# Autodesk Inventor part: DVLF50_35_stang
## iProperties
Created: 2010-03
Part Number: DVLF50_35_stang
Document SubType Name: Modeling
Designer: TB
Mass: 264.807 g
Surface Area: 314.569 cm^2
Volume: 264.807 cm^3
Density: 1 g/cm^3
Author: TB
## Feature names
1. Revolution1
2. Fillet1
3. Revolution2
